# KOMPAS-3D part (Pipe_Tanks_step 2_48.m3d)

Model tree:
1. X Axis
2. Y Axis
3. Z Axis  (labels: Pipe Dn 50)
     Òîëùèíà ñòåíêè 1 = 1

Referenced files in C:\Documents and Settings\kashirsky\Мои документы\Camtasia Studio\Pipelines3D\Tanks\: Tanks_step 2.a3d
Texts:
  Pipe Dn 50
  Steel ASTM A295
  Three Point Plane
  Plane at Angle
  Line and Point Plane
  Axis through Two Vertices
  Axis of Feature
  Axis of Conical Surface
  Axis through Edge
  Trim by Surface
  Trim by Sketch
  Feature with No History
  Intersection Axis of Two Planes
  Two Line Plane
  Line and Face Plane
  Bend by line
  Hole in sheet body
  Cut in sheet body
  Point in CM
  Linear Dimension from Line to Point
  Surface Finish Symbol
  Geometric Tolerance Symbol
  Leader #1
  Leader #2
  Leader #3
  Shape Deviations and Datum
  Node point number
  Mark of coordination axis
  Node point designation
  Mark/Reference designation with leader
  Mark/reference designation on line
  Mark/Reference designation without leader
  Plane of section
